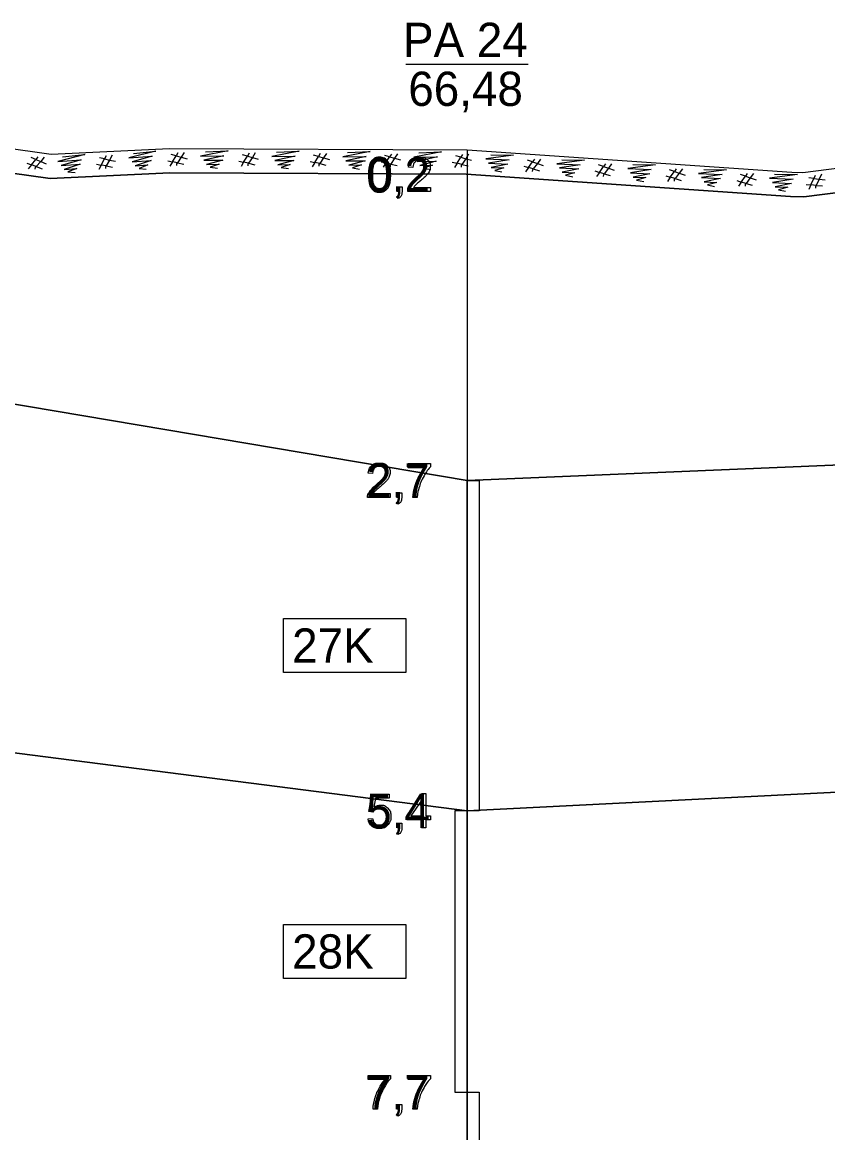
# Model space of a CAD drawing. Extents: x 532503 to 539665, y 6557663 to 6561526.
# Drawn here: x 537854.5 to 537986.3, y 6560330.8 to 6560512.4 of the extents above; entities that cross this region are included whole.
import ezdxf

# ---------------------------------------------------------------- set-up
doc = ezdxf.new("R2010")
doc.units = 0
for name, color, linetype in [('Default', 7, 'Continuous'), ('GEOLPUNKT', 7, 'Continuous'), ('Plokid', 7, 'Continuous'), ('Proovid', 7, 'Continuous'), ('Täide', 7, 'Continuous')]:
    doc.layers.add(name, color=color, linetype=linetype)

msp = doc.modelspace()

# ---------------------------------------------------------------- linework, layer by layer
at = {"layer": 'Default'}
for points in [[(537680.4, 6560509.07), (537723.67, 6560510.21), (537730.2, 6560509.2), (537732.65, 6560508.76), (537734.04, 6560508.45), (537736.5, 6560507.8), (537737.5, 6560507.51), (537739.73, 6560506.73), (537740.88, 6560506.27), (537741.97, 6560505.69), (537743.13, 6560505.01), (537745.1, 6560503.73), (537768.7, 6560491.57), (537801.81, 6560492.59), (537816.56, 6560492.51), (537822.85, 6560492.99), (537833.97, 6560493.33), (537843.11, 6560493.06), (537859.31, 6560490.78), (537878.61, 6560491.73), (537927.28, 6560491.47), (537980.37, 6560487.85), (537982.17, 6560487.79), (538002.16, 6560490.36)], [(537680.4, 6560503.07), (537729.54, 6560505.28), (537731.86, 6560504.86), (537733.1, 6560504.58), (537735.43, 6560503.97), (537736.27, 6560503.72), (537738.34, 6560503), (537739.21, 6560502.66), (537740.03, 6560502.22), (537741.03, 6560501.63), (537743.11, 6560500.28), (537767.8, 6560487.57), (537801.86, 6560488.61), (537816.7, 6560488.53), (537823.06, 6560489.02), (537833.97, 6560489.36), (537842.78, 6560489.09), (537859.13, 6560486.79), (537878.7, 6560487.75), (537927.13, 6560487.49), (537980.16, 6560483.88), (537982.35, 6560483.8), (538002.08, 6560486.34)], [(537114.82, 6560272.67), (537235.3, 6560321.87), (537242.05, 6560326.27), (537267.99, 6560346.27), (537409.98, 6560463.67), (537409.98, 6560463.67), (537409.98, 6560463.67), (537680.4, 6560479.07), (537680.4, 6560479.07), (537927.28, 6560437.47), (537927.28, 6560437.47), (538157.31, 6560447.07), (538157.31, 6560447.07), (538426.58, 6560436.27), (538426.58, 6560436.27), (538556.7, 6560436.87), (538556.7, 6560436.87), (538783.9, 6560390.27), (538783.9, 6560390.27)], [(537409.98, 6560463.67), (537409.98, 6560463.67), (537680.4, 6560479.07), (537680.4, 6560479.07), (537927.28, 6560437.47), (537927.28, 6560437.47), (538157.31, 6560447.07), (538157.31, 6560447.07), (538426.58, 6560436.27), (538426.58, 6560436.27), (538556.7, 6560436.87), (538556.7, 6560436.87), (538783.9, 6560390.27), (538809.14, 6560385.09)], [(537327.58, 6560397.59), (537409.98, 6560401.67), (537680.4, 6560415.07), (537927.28, 6560383.47), (538157.31, 6560395.07), (538426.58, 6560390.27), (538556.7, 6560374.87), (538783.9, 6560390.27), (538809.14, 6560385.09)]]:
    msp.add_lwpolyline(points, dxfattribs=at)
at = {"layer": 'GEOLPUNKT'}
for p, q in [((537917.28, 6560505.47), (537937.28, 6560505.47)), ((537927.28, 6560491.47), (537927.28, 6560223.47))]:
    msp.add_line(p, q, dxfattribs=at)
at = {"layer": 'Plokid'}
for points in [[(537680.4, 6560503.07), (537729.54, 6560505.28), (537731.86, 6560504.86), (537733.1, 6560504.58), (537735.43, 6560503.97), (537736.27, 6560503.72), (537738.34, 6560503), (537739.21, 6560502.66), (537740.03, 6560502.22), (537741.03, 6560501.63), (537743.11, 6560500.28), (537767.8, 6560487.57), (537801.86, 6560488.61), (537816.7, 6560488.53), (537823.06, 6560489.02), (537833.97, 6560489.36), (537842.78, 6560489.09), (537859.13, 6560486.79), (537878.7, 6560487.75), (537927.13, 6560487.49), (537980.16, 6560483.88), (537982.35, 6560483.8), (538002.08, 6560486.34)], [(537119.21, 6560274.46), (537235.3, 6560321.87), (537242.05, 6560326.27), (537267.99, 6560346.27), (537291.08, 6560365.36), (537409.98, 6560463.67), (537409.98, 6560463.67), (537680.4, 6560479.07), (537680.4, 6560479.07), (537927.28, 6560437.47), (537927.28, 6560437.47), (538157.31, 6560447.07), (538157.31, 6560447.07), (538426.58, 6560436.27), (538426.58, 6560436.27), (538556.7, 6560436.87), (538556.7, 6560436.87), (538783.9, 6560390.27), (538783.9, 6560390.27)]]:
    msp.add_lwpolyline(points, dxfattribs=at)
at = {"layer": 'Proovid'}
for points in [[(537918.41, 6560488.6), (537917.71, 6560488.67)], [(537915.87, 6560484.67), (537915.87, 6560485.45), (537916.65, 6560485.45), (537916.65, 6560484.67)], [(537916.25, 6560484.67), (537915.87, 6560484.67)], [(537921.28, 6560485.33), (537921.28, 6560484.67), (537917.58, 6560484.67)], [(537918.53, 6560485.33), (537921.28, 6560485.33)], [(537916.01, 6560483.56), (537915.82, 6560483.85)], [(537917.65, 6560439.54), (537917.65, 6560440.2), (537921.28, 6560440.2), (537921.28, 6560439.66)], [(537920.39, 6560439.54), (537917.65, 6560439.54)], [(537911.83, 6560438.6), (537911.12, 6560438.67)], [(537914.7, 6560435.33), (537914.7, 6560434.67), (537911, 6560434.67)], [(537911.95, 6560435.33), (537914.7, 6560435.33)], [(537915.95, 6560433.56), (537915.76, 6560433.85)], [(537915.81, 6560434.67), (537915.81, 6560435.45), (537916.59, 6560435.45), (537916.59, 6560434.67)], [(537916.2, 6560434.67), (537915.81, 6560434.67)], [(537919.14, 6560434.67), (537918.44, 6560434.67)], [(537911.88, 6560383.24), (537911.24, 6560383.32), (537911.78, 6560386.2), (537914.56, 6560386.2), (537914.56, 6560385.54), (537912.33, 6560385.54), (537912.03, 6560384.04)], [(537919.84, 6560380.67), (537919.84, 6560382.01), (537917.41, 6560382.01), (537917.41, 6560382.64), (537919.96, 6560386.27), (537920.52, 6560386.27), (537920.52, 6560382.64), (537921.28, 6560382.64), (537921.28, 6560382.01), (537920.52, 6560382.01), (537920.52, 6560380.67), (537919.84, 6560380.67)], [(537919.84, 6560382.64), (537919.84, 6560385.17), (537918.08, 6560382.64), (537919.84, 6560382.64)], [(537911.11, 6560382.14), (537911.83, 6560382.2)], [(537915.83, 6560380.67), (537915.83, 6560381.45), (537916.61, 6560381.45), (537916.61, 6560380.67)], [(537915.98, 6560379.56), (537915.79, 6560379.85)], [(537916.22, 6560380.67), (537915.83, 6560380.67)], [(537911.13, 6560339.54), (537911.13, 6560340.2), (537914.76, 6560340.2), (537914.76, 6560339.66)], [(537913.87, 6560339.54), (537911.13, 6560339.54)], [(537917.65, 6560339.54), (537917.65, 6560340.2), (537921.28, 6560340.2), (537921.28, 6560339.66)], [(537920.39, 6560339.54), (537917.65, 6560339.54)], [(537912.62, 6560334.67), (537911.91, 6560334.67)], [(537915.81, 6560334.67), (537915.81, 6560335.45), (537916.59, 6560335.45), (537916.59, 6560334.67)], [(537916.2, 6560334.67), (537915.81, 6560334.67)], [(537919.14, 6560334.67), (537918.44, 6560334.67)], [(537915.95, 6560333.56), (537915.76, 6560333.85)]]:
    msp.add_lwpolyline(points, dxfattribs=at)
for points in [[(537927.28, 6560437.47), (537929.28, 6560437.47), (537929.28, 6560383.47), (537927.28, 6560383.47)], [(537897.28, 6560414.87), (537917.28, 6560414.87), (537917.28, 6560406.07), (537897.28, 6560406.07)], [(537927.28, 6560383.47), (537925.28, 6560383.47), (537925.28, 6560337.47), (537927.28, 6560337.47)], [(537897.28, 6560364.87), (537917.28, 6560364.87), (537917.28, 6560356.07), (537897.28, 6560356.07)], [(537927.28, 6560337.47), (537929.28, 6560337.47), (537929.28, 6560311.47), (537927.28, 6560311.47)]]:
    msp.add_lwpolyline(points, close=True, dxfattribs=at)
for points in [[(537911.15, 6560487.43), (537911.15, 6560488.42), (537911.35, 6560489.03), (537911.55, 6560489.64), (537911.96, 6560489.96), (537912.36, 6560490.29), (537912.97, 6560490.29), (537913.42, 6560490.29), (537913.76, 6560490.11), (537914.1, 6560489.93), (537914.32, 6560489.59), (537914.54, 6560489.25), (537914.67, 6560488.75), (537914.79, 6560488.26), (537914.79, 6560487.43), (537914.79, 6560486.45), (537914.59, 6560485.84), (537914.39, 6560485.23), (537913.99, 6560484.91), (537913.58, 6560484.58), (537912.97, 6560484.58), (537912.16, 6560484.58), (537911.7, 6560485.15), (537911.15, 6560485.86), (537911.15, 6560487.43)], [(537917.71, 6560488.67), (537917.78, 6560489.46), (537918.25, 6560489.88), (537918.73, 6560490.29), (537919.52, 6560490.29), (537920.33, 6560490.29), (537920.8, 6560489.84), (537921.27, 6560489.4), (537921.27, 6560488.74), (537921.27, 6560488.4), (537921.13, 6560488.08), (537921, 6560487.75), (537920.68, 6560487.39), (537920.36, 6560487.04), (537919.62, 6560486.41), (537919, 6560485.89), (537918.82, 6560485.7), (537918.65, 6560485.52), (537918.53, 6560485.33)], [(537911.85, 6560487.43), (537911.85, 6560486.05), (537912.18, 6560485.6), (537912.5, 6560485.14), (537912.97, 6560485.14), (537913.44, 6560485.14), (537913.76, 6560485.6), (537914.09, 6560486.05), (537914.09, 6560487.43), (537914.09, 6560488.81), (537913.76, 6560489.27), (537913.44, 6560489.72), (537912.96, 6560489.72), (537912.49, 6560489.72), (537912.21, 6560489.32), (537911.85, 6560488.81), (537911.85, 6560487.43)], [(537917.58, 6560484.67), (537917.57, 6560484.92), (537917.66, 6560485.15), (537917.8, 6560485.53), (537918.11, 6560485.89), (537918.42, 6560486.26), (537919.01, 6560486.74), (537919.92, 6560487.49), (537920.24, 6560487.93), (537920.56, 6560488.36), (537920.56, 6560488.75), (537920.56, 6560489.16), (537920.27, 6560489.44), (537919.98, 6560489.72), (537919.51, 6560489.72), (537919.01, 6560489.72), (537918.72, 6560489.43), (537918.42, 6560489.13), (537918.41, 6560488.6)], [(537915.82, 6560483.85), (537916.04, 6560483.95), (537916.14, 6560484.14), (537916.24, 6560484.32), (537916.25, 6560484.67)], [(537916.65, 6560484.67), (537916.65, 6560484.24), (537916.49, 6560483.97), (537916.34, 6560483.71), (537916.01, 6560483.56)], [(537911, 6560434.67), (537910.99, 6560434.92), (537911.08, 6560435.15), (537911.22, 6560435.53), (537911.53, 6560435.89), (537911.84, 6560436.26), (537912.43, 6560436.74), (537913.34, 6560437.49), (537913.66, 6560437.93), (537913.98, 6560438.36), (537913.98, 6560438.75), (537913.98, 6560439.16), (537913.69, 6560439.44), (537913.4, 6560439.72), (537912.93, 6560439.72), (537912.43, 6560439.72), (537912.13, 6560439.43), (537911.84, 6560439.13), (537911.83, 6560438.6)], [(537911.12, 6560438.67), (537911.2, 6560439.46), (537911.67, 6560439.88), (537912.14, 6560440.29), (537912.94, 6560440.29), (537913.75, 6560440.29), (537914.22, 6560439.84), (537914.69, 6560439.4), (537914.69, 6560438.74), (537914.69, 6560438.4), (537914.55, 6560438.08), (537914.41, 6560437.75), (537914.09, 6560437.39), (537913.78, 6560437.04), (537913.04, 6560436.41), (537912.42, 6560435.89), (537912.24, 6560435.7), (537912.07, 6560435.52), (537911.95, 6560435.33)], [(537918.44, 6560434.67), (537918.45, 6560435.33), (537918.7, 6560436.27), (537918.94, 6560437.2), (537919.41, 6560438.07), (537919.87, 6560438.94), (537920.39, 6560439.54)], [(537921.28, 6560439.66), (537920.74, 6560439.09), (537920.22, 6560438.15), (537919.69, 6560437.21), (537919.41, 6560436.21), (537919.2, 6560435.51), (537919.14, 6560434.67)], [(537915.76, 6560433.85), (537915.98, 6560433.95), (537916.08, 6560434.14), (537916.18, 6560434.32), (537916.2, 6560434.67)], [(537916.59, 6560434.67), (537916.59, 6560434.24), (537916.44, 6560433.97), (537916.28, 6560433.71), (537915.95, 6560433.56)], [(537912.03, 6560384.04), (537912.53, 6560384.39), (537913.08, 6560384.39), (537913.82, 6560384.39), (537914.32, 6560383.88), (537914.82, 6560383.37), (537914.82, 6560382.57), (537914.82, 6560381.81), (537914.38, 6560381.26), (537913.84, 6560380.58), (537912.91, 6560380.58), (537912.15, 6560380.58), (537911.66, 6560381), (537911.18, 6560381.43), (537911.11, 6560382.14)], [(537911.83, 6560382.2), (537911.91, 6560381.67), (537912.2, 6560381.41), (537912.5, 6560381.14), (537912.91, 6560381.14), (537913.41, 6560381.14), (537913.75, 6560381.51), (537914.09, 6560381.89), (537914.09, 6560382.51), (537914.09, 6560383.1), (537913.77, 6560383.44), (537913.44, 6560383.78), (537912.9, 6560383.78), (537912.56, 6560383.78), (537912.3, 6560383.63), (537912.03, 6560383.48), (537911.88, 6560383.24)], [(537915.79, 6560379.85), (537916, 6560379.95), (537916.11, 6560380.14), (537916.21, 6560380.32), (537916.22, 6560380.67)], [(537916.61, 6560380.67), (537916.61, 6560380.24), (537916.46, 6560379.97), (537916.31, 6560379.71), (537915.98, 6560379.56)], [(537911.91, 6560334.67), (537911.93, 6560335.33), (537912.17, 6560336.27), (537912.42, 6560337.2), (537912.89, 6560338.07), (537913.35, 6560338.94), (537913.87, 6560339.54)], [(537914.76, 6560339.66), (537914.22, 6560339.09), (537913.7, 6560338.15), (537913.17, 6560337.21), (537912.89, 6560336.21), (537912.68, 6560335.51), (537912.62, 6560334.67)], [(537918.44, 6560334.67), (537918.45, 6560335.33), (537918.7, 6560336.27), (537918.94, 6560337.2), (537919.41, 6560338.07), (537919.87, 6560338.94), (537920.39, 6560339.54)], [(537921.28, 6560339.66), (537920.74, 6560339.09), (537920.22, 6560338.15), (537919.69, 6560337.21), (537919.41, 6560336.21), (537919.2, 6560335.51), (537919.14, 6560334.67)], [(537915.76, 6560333.85), (537915.98, 6560333.95), (537916.08, 6560334.14), (537916.18, 6560334.32), (537916.2, 6560334.67)], [(537916.59, 6560334.67), (537916.59, 6560334.24), (537916.44, 6560333.97), (537916.28, 6560333.71), (537915.95, 6560333.56)]]:
    msp.add_open_spline(points, degree=3, dxfattribs=at)
at = {"layer": 'Täide'}
for p, q in [((537680.4, 6560479.07), (537927.28, 6560437.47)), ((537927.28, 6560437.47), (538157.31, 6560447.07))]:
    msp.add_line(p, q, dxfattribs=at)
for points in [[(538002.08, 6560486.34), (537982.35, 6560483.8), (537980.16, 6560483.88), (537927.13, 6560487.49), (537878.7, 6560487.75), (537859.13, 6560486.79), (537842.78, 6560489.09), (537833.97, 6560489.36), (537823.06, 6560489.02), (537816.7, 6560488.53), (537801.86, 6560488.61), (537767.8, 6560487.57), (537743.11, 6560500.28), (537741.03, 6560501.63), (537740.03, 6560502.22), (537739.21, 6560502.66), (537738.34, 6560503), (537736.27, 6560503.72), (537735.43, 6560503.97), (537733.1, 6560504.58), (537731.86, 6560504.86), (537729.54, 6560505.28), (537680.4, 6560503.07)], [(537856.69, 6560488.33), (537856.74, 6560488.63), (537856.83, 6560488.75), (537856.06, 6560489.04), (537856.79, 6560489.93), (537856.02, 6560490.25)], [(537857.13, 6560490.35), (537856.79, 6560489.93), (537857.57, 6560489.6), (537858.49, 6560489.21)], [(537858.14, 6560490.27), (537857.57, 6560489.6), (537856.83, 6560488.75), (537857.81, 6560488.38)], [(537861.11, 6560490.34), (537864.81, 6560490.72), (537860.37, 6560489.59), (537864.18, 6560489.88), (537860.91, 6560488.96), (537864.03, 6560489.16), (537861.42, 6560488.3), (537863.47, 6560488.47), (537862.03, 6560487.89), (537863.21, 6560487.77)], [(537868.21, 6560488.42), (537868.2, 6560488.72), (537868.27, 6560488.86), (537867.45, 6560489), (537868, 6560490.01), (537867.18, 6560490.18)], [(537868.26, 6560490.49), (537868, 6560490.01), (537868.84, 6560489.83), (537869.81, 6560489.63)], [(537869.27, 6560490.6), (537868.84, 6560489.83), (537868.27, 6560488.86), (537869.29, 6560488.68)], [(537872.72, 6560490.91), (537876.42, 6560491.28), (537871.98, 6560490.16), (537875.79, 6560490.45), (537872.53, 6560489.53), (537875.65, 6560489.73), (537873.04, 6560488.86), (537875.09, 6560489.04), (537873.65, 6560488.46), (537874.83, 6560488.34)], [(537879.85, 6560488.92), (537879.85, 6560489.23), (537879.93, 6560489.36), (537879.12, 6560489.55), (537879.73, 6560490.53), (537878.92, 6560490.74)], [(537880.01, 6560490.99), (537879.73, 6560490.53), (537880.55, 6560490.3), (537881.51, 6560490.04)], [(537881.02, 6560491.04), (537880.55, 6560490.3), (537879.93, 6560489.36), (537880.95, 6560489.13)], [(537884.49, 6560491.17), (537888.2, 6560491.34), (537883.71, 6560490.46), (537887.53, 6560490.54), (537884.22, 6560489.8), (537887.35, 6560489.83), (537884.69, 6560489.11), (537886.75, 6560489.17), (537885.28, 6560488.67), (537886.45, 6560488.49)], [(537891.48, 6560488.86), (537891.48, 6560489.17), (537891.56, 6560489.3), (537890.75, 6560489.49), (537891.36, 6560490.46), (537890.55, 6560490.68)], [(537891.64, 6560490.93), (537891.36, 6560490.46), (537892.18, 6560490.24), (537893.14, 6560489.98)], [(537892.65, 6560490.98), (537892.18, 6560490.24), (537891.56, 6560489.3), (537892.57, 6560489.06)], [(537896.12, 6560491.1), (537899.83, 6560491.28), (537895.34, 6560490.4), (537899.16, 6560490.48), (537895.85, 6560489.73), (537898.98, 6560489.77), (537896.32, 6560489.05), (537898.38, 6560489.11), (537896.91, 6560488.61), (537898.08, 6560488.43)], [(537903.11, 6560488.8), (537903.11, 6560489.11), (537903.19, 6560489.24), (537902.38, 6560489.42), (537902.99, 6560490.4), (537902.18, 6560490.62)], [(537903.27, 6560490.87), (537902.99, 6560490.4), (537903.81, 6560490.18), (537904.77, 6560489.92)], [(537904.28, 6560490.92), (537903.81, 6560490.18), (537903.19, 6560489.24), (537904.2, 6560489)], [(537907.74, 6560491.04), (537911.46, 6560491.22), (537906.96, 6560490.34), (537910.79, 6560490.41), (537907.48, 6560489.67), (537910.61, 6560489.71), (537907.95, 6560488.98), (537910.01, 6560489.05), (537908.54, 6560488.54), (537909.71, 6560488.36)], [(537914.74, 6560488.74), (537914.74, 6560489.04), (537914.82, 6560489.17), (537914.01, 6560489.36), (537914.62, 6560490.34), (537913.81, 6560490.56)], [(537914.9, 6560490.81), (537914.62, 6560490.34), (537915.44, 6560490.12), (537916.39, 6560489.86)], [(537915.91, 6560490.86), (537915.44, 6560490.12), (537914.82, 6560489.17), (537915.83, 6560488.94)], [(537919.37, 6560490.98), (537923.09, 6560491.16), (537918.59, 6560490.27), (537922.42, 6560490.35), (537919.11, 6560489.61), (537922.23, 6560489.64), (537919.58, 6560488.92), (537921.64, 6560488.99), (537920.17, 6560488.48), (537921.34, 6560488.3)], [(537926.37, 6560488.68), (537926.37, 6560488.98), (537926.45, 6560489.11), (537925.64, 6560489.3), (537926.24, 6560490.28), (537925.44, 6560490.49)], [(537926.53, 6560490.75), (537926.24, 6560490.28), (537927.06, 6560490.05), (537928.02, 6560489.8)], [(537927.54, 6560490.79), (537927.06, 6560490.05), (537926.45, 6560489.11), (537927.46, 6560488.88)], [(537931.16, 6560490.67), (537934.88, 6560490.62), (537930.34, 6560490.02), (537934.16, 6560489.86), (537930.81, 6560489.32), (537933.93, 6560489.16), (537931.24, 6560488.61), (537933.29, 6560488.54), (537931.8, 6560488.13), (537932.95, 6560487.88)], [(537938.29, 6560489.99), (537937.97, 6560489.54), (537938.78, 6560489.27), (537939.72, 6560488.95)], [(537855.32, 6560489.32), (537856.06, 6560489.04), (537855.53, 6560488.39)], [(537866.67, 6560489.14), (537867.45, 6560489), (537867.06, 6560488.26)], [(537878.35, 6560489.72), (537879.12, 6560489.55), (537878.69, 6560488.83)], [(537889.98, 6560489.66), (537890.75, 6560489.49), (537890.32, 6560488.77)], [(537901.61, 6560489.6), (537902.38, 6560489.42), (537901.95, 6560488.71)], [(537913.24, 6560489.54), (537914.01, 6560489.36), (537913.57, 6560488.64)], [(537924.87, 6560489.48), (537925.64, 6560489.3), (537925.2, 6560488.58)], [(537936.55, 6560488.83), (537937.31, 6560488.6), (537936.83, 6560487.92)], [(537937.99, 6560487.94), (537938.02, 6560488.24), (537938.1, 6560488.37), (537937.31, 6560488.6), (537937.97, 6560489.54), (537937.18, 6560489.81)], [(537939.3, 6560489.98), (537938.78, 6560489.27), (537938.1, 6560488.37), (537939.1, 6560488.07)], [(537942.76, 6560489.88), (537946.48, 6560489.83), (537941.94, 6560489.23), (537945.76, 6560489.06), (537942.41, 6560488.53), (537945.53, 6560488.37), (537942.84, 6560487.82), (537944.9, 6560487.75), (537943.4, 6560487.34), (537944.56, 6560487.09)], [(537949.6, 6560487.15), (537949.62, 6560487.45), (537949.7, 6560487.58), (537948.91, 6560487.81), (537949.58, 6560488.75), (537948.78, 6560489.02)], [(537949.89, 6560489.2), (537949.58, 6560488.75), (537950.38, 6560488.48), (537951.32, 6560488.16)], [(537950.9, 6560489.19), (537950.38, 6560488.48), (537949.7, 6560487.58), (537950.7, 6560487.28)], [(537954.36, 6560489.09), (537958.08, 6560489.04), (537953.54, 6560488.44), (537957.36, 6560488.27), (537954.01, 6560487.74), (537957.14, 6560487.58), (537954.44, 6560487.03), (537956.5, 6560486.96), (537955, 6560486.55), (537956.16, 6560486.3)], [(537961.2, 6560486.36), (537961.22, 6560486.66), (537961.31, 6560486.79), (537960.51, 6560487.02), (537961.18, 6560487.96), (537960.38, 6560488.23)], [(537961.49, 6560488.41), (537961.18, 6560487.96), (537961.98, 6560487.69), (537962.92, 6560487.37)], [(537962.5, 6560488.4), (537961.98, 6560487.69), (537961.31, 6560486.79), (537962.3, 6560486.49)], [(537965.97, 6560488.3), (537969.69, 6560488.25), (537965.14, 6560487.65), (537968.96, 6560487.48), (537965.62, 6560486.95), (537968.74, 6560486.79), (537966.04, 6560486.24), (537968.1, 6560486.17), (537966.6, 6560485.76), (537967.76, 6560485.51)], [(537948.15, 6560488.04), (537948.91, 6560487.81), (537948.43, 6560487.12)], [(537959.75, 6560487.25), (537960.51, 6560487.02), (537960.03, 6560486.33)], [(537971.36, 6560486.46), (537972.11, 6560486.23), (537971.63, 6560485.54)], [(537972.8, 6560485.57), (537972.82, 6560485.87), (537972.91, 6560486), (537972.11, 6560486.23), (537972.78, 6560487.17), (537971.99, 6560487.44)], [(537973.09, 6560487.62), (537972.78, 6560487.17), (537973.59, 6560486.9), (537974.53, 6560486.58)], [(537974.1, 6560487.61), (537973.59, 6560486.9), (537972.91, 6560486), (537973.91, 6560485.7)], [(537977.57, 6560487.51), (537981.29, 6560487.45), (537976.75, 6560486.86), (537980.57, 6560486.69), (537977.22, 6560486.16), (537980.34, 6560486), (537977.65, 6560485.45), (537979.7, 6560485.38), (537978.2, 6560484.97), (537979.36, 6560484.72)], [(537984.32, 6560485.24), (537984.28, 6560485.54), (537984.34, 6560485.68), (537983.51, 6560485.76), (537983.98, 6560486.81), (537983.15, 6560486.92)], [(537984.2, 6560487.31), (537983.98, 6560486.81), (537984.83, 6560486.7), (537985.81, 6560486.57)], [(537985.2, 6560487.5), (537984.83, 6560486.7), (537984.34, 6560485.68), (537985.37, 6560485.59)], [(537982.72, 6560485.83), (537983.51, 6560485.76), (537983.18, 6560484.99)], [(538783.9, 6560390.27), (538783.9, 6560390.27), (538556.7, 6560436.87), (538426.58, 6560436.27), (538157.31, 6560447.07), (537927.28, 6560437.47), (537680.4, 6560479.07), (537409.98, 6560463.67), (537387.62, 6560462.4)], [(538809.14, 6560385.09), (538783.9, 6560390.27), (538556.7, 6560436.87), (538426.58, 6560436.27), (538157.31, 6560447.07), (537927.28, 6560437.47), (537680.4, 6560479.07), (537409.98, 6560463.67), (537409.98, 6560463.67)], [(537327.58, 6560397.59), (537409.98, 6560401.67), (537680.4, 6560415.07), (537927.28, 6560383.47), (538157.31, 6560395.07), (538426.58, 6560390.27), (538556.7, 6560374.87), (538556.7, 6560374.87), (538556.7, 6560374.87)], [(538783.9, 6560390.27), (538556.7, 6560374.87), (538426.58, 6560390.27), (538157.31, 6560395.07), (537927.28, 6560383.47), (537680.4, 6560415.07)]]:
    msp.add_lwpolyline(points, dxfattribs=at)

# ---------------------------------------------------------------- texts
at = {"layer": 'GEOLPUNKT'}
for s, p in [('PA 24', (537916.81, 6560506.67)), ('66,48', (537917.67, 6560498.67))]:
    msp.add_text(s, height=5.6, dxfattribs=at).set_placement(p)
at = {"layer": 'Proovid'}
for s, p in [('0,2', (537910.82, 6560484.67)), ('2,7', (537910.76, 6560434.67)), ('27K', (537898.68, 6560407.67)), ('5,4', (537910.79, 6560380.67)), ('28K', (537898.68, 6560357.67)), ('7,7', (537910.76, 6560334.67))]:
    msp.add_text(s, height=5.6, dxfattribs=at).set_placement(p)

doc.saveas('drawing.dxf')
